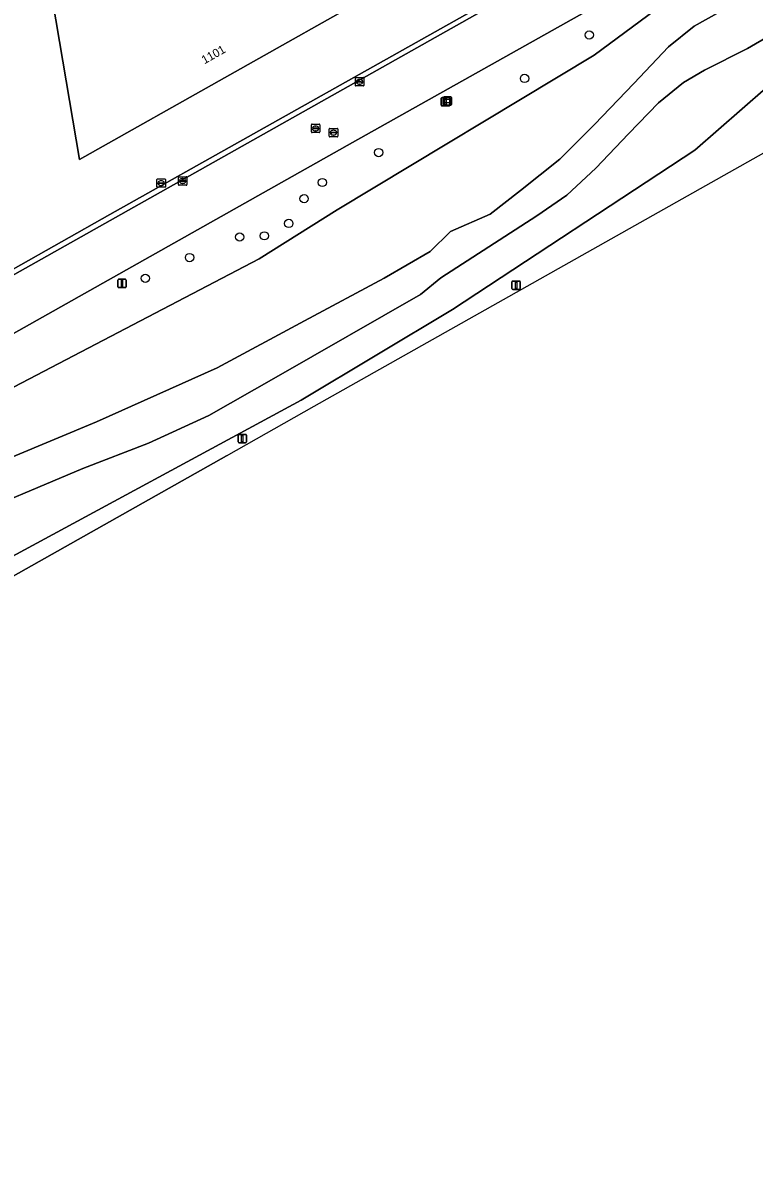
# Model space of a CAD drawing. Extents: x 154324 to 155744, y 382937 to 384188.
# Drawn here: x 154883.8 to 154970, y 383044.6 to 383179.9 of the extents above; entities that cross this region are included whole.
import ezdxf

# ---------------------------------------------------------------- set-up
doc = ezdxf.new("R2010")
doc.units = 0
for name, color, linetype in [('IMGEO_Berm_groen', 7, 'Continuous'), ('IMGEO_Boom', 7, 'Continuous'), ('IMGEO_Brandkraan', 7, 'Continuous'), ('IMGEO_Erf', 7, 'Continuous'), ('IMGEO_Fietspad_gesloten', 7, 'Continuous'), ('IMGEO_Greppel_droge_sloot', 7, 'Continuous'), ('IMGEO_Kolk', 7, 'Continuous'), ('IMGEO_Lichtmast', 7, 'Continuous'), ('IMGEO_Oever', 7, 'Continuous'), ('IMGEO_Pand', 7, 'Continuous'), ('IMGEO_Pand_nummerreeks', 7, 'Continuous'), ('IMGEO_Rijbaan_lokaal_gesloten', 7, 'Continuous'), ('IMGEO_Rijbaan_lokaal_open', 7, 'Continuous'), ('IMGEO_Rioolput', 7, 'Continuous'), ('IMGEO_Verklikker', 7, 'Continuous')]:
    doc.layers.add(name, color=color, linetype=linetype)

msp = doc.modelspace()

# ---------------------------------------------------------------- linework, layer by layer
at = {"layer": 'IMGEO_Berm_groen'}
for points in [[(154991.53, 383204.59), (154991.29, 383204.47), (154988.64, 383202.93), (154972.99, 383194.07), (154922.65, 383165.82), (154870.56, 383136.48), (154807.99, 383101.45), (154807.41, 383100.98), (154799.35, 383096.59), (154796.65, 383095.02), (154788.62, 383090.34), (154781.16, 383085.99), (154710.18, 383044.63)], [(154808.49, 383100.65), (154810.32, 383101.66), (154812.35, 383102.26), (154814.01, 383102.45), (154825.93, 383109.31), (154838.85, 383113.67), (154847.48, 383118.93), (154880.08, 383135.61), (154911.65, 383152.09), (154920.84, 383157.86), (154951.17, 383176.1), (154968.51, 383188.95), (154984.99, 383198.51)], [(154997.79, 383187.52), (154995.02, 383185.46), (154993.14, 383185.64), (154991.72, 383185.98), (154990.93, 383185.04), (154990.62, 383183.53), (154987.22, 383179.75), (154971.41, 383172.23), (154963.03, 383164.91), (154934.46, 383146.12), (154916.59, 383135.42), (154881.58, 383116.49), (154841.44, 383095.73), (154819.25, 383088.82), (154813.1, 383089.87), (154809.33, 383090.4), (154807.25, 383092.6)], [(154806.83, 383071.94), (154907.79, 383128.86), (154918.15, 383134.7), (155000, 383180.84), (155003.66, 383182.91), (155010.14, 383186.73)]]:
    msp.add_lwpolyline(points, dxfattribs=at)
at = {"layer": 'IMGEO_Boom'}
for centre in [(154950.59, 383178.49), (154942.96, 383173.36), (154925.75, 383164.62), (154919.11, 383161.09), (154916.95, 383159.18), (154915.15, 383156.26), (154909.36, 383154.66), (154912.27, 383154.8), (154903.44, 383152.24), (154898.23, 383149.79)]:
    msp.add_circle(centre, 0.489, dxfattribs=at)
at = {"layer": 'IMGEO_Brandkraan'}
for p, q in [((154899.67, 383161.52), (154900.52, 383161.52)), ((154899.59, 383160.59), (154899.59, 383161.44)), ((154900.52, 383160.52), (154899.67, 383160.52)), ((154899.85, 383161.01), (154899.85, 383161.02)), ((154900.29, 383160.97), (154899.89, 383160.97)), ((154899.9, 383161.06), (154900.29, 383161.06)), ((154900.08, 383161.3), (154900.11, 383161.3)), ((154900.1, 383160.74), (154900.08, 383160.74)), ((154900.34, 383161.02), (154900.34, 383161.01)), ((154900.6, 383161.44), (154900.6, 383160.59))]:
    msp.add_line(p, q, dxfattribs=at)
for points in [[(154899.67, 383161.52), (154900.52, 383161.52)], [(154899.59, 383160.59), (154899.59, 383161.44)], [(154900.52, 383160.52), (154899.67, 383160.52)], [(154900.6, 383161.44), (154900.6, 383160.59)]]:
    msp.add_lwpolyline(points, dxfattribs=at)
for centre, radius, start, end in [((154899.67, 383161.44), 0.0765, 91.552, 178.448), ((154899.67, 383161.44), 0.0765, 91.552, 178.448), ((154900.52, 383161.44), 0.0765, 1.552, 88.448), ((154900.52, 383161.44), 0.0765, 1.552, 88.448), ((154899.67, 383160.59), 0.0765, 181.552, 268.448), ((154899.67, 383160.59), 0.0765, 181.552, 268.448), ((154899.89, 383161.02), 0.0403, 85.8775, 175.7526), ((154899.89, 383161.01), 0.0366, 178.938, 274.7102), ((154900.3, 383161.02), 0.0386, 1.7309, 96.639), ((154900.29, 383161.02), 0.043, 264.8664, 352.4533), ((154900.52, 383160.59), 0.0765, 271.552, 358.448), ((154900.52, 383160.59), 0.0765, 271.552, 358.448)]:
    msp.add_arc(centre, radius, start, end, dxfattribs=at)
for centre, major_axis, ratio, start_param, end_param in [((154900.08, 383161.02), (-0.387, 0.002), 0.722429, 4.712389, 7.853982), ((154900.11, 383161.02), (-0.39, 0.002), 0.717154, 1.570796, 4.712389)]:
    msp.add_ellipse(centre, major_axis=major_axis, ratio=ratio, start_param=start_param, end_param=end_param, dxfattribs=at)
at = {"layer": 'IMGEO_Erf'}
for points in [[(154925.91, 383183.81), (154890.47, 383163.81), (154885.3, 383194.22)], [(154813.97, 383112.22), (154836.96, 383125.07), (154866.96, 383142.01), (154876.91, 383147.63), (154894.04, 383157.31), (154944.86, 383185.9), (154948.91, 383188.11)]]:
    msp.add_lwpolyline(points, dxfattribs=at)
at = {"layer": 'IMGEO_Fietspad_gesloten'}
msp.add_lwpolyline([(154806.83, 383071.94), (154907.79, 383128.86), (154806.83, 383071.94), (154806.83, 383071.94)], dxfattribs=at)
at = {"layer": 'IMGEO_Greppel_droge_sloot'}
for points in [[(154967.67, 383182.15), (154962.95, 383179.53), (154959.93, 383177.1), (154955.85, 383172.76), (154951.2, 383167.94), (154947.13, 383163.84), (154942.48, 383160.15), (154938.92, 383157.34), (154934.23, 383155.33), (154931.84, 383152.94), (154926.39, 383149.8), (154917.01, 383144.77), (154906.7, 383139.24), (154892.46, 383132.87), (154882.48, 383128.68), (154872.51, 383124.16), (154861.95, 383119.21), (154853.15, 383115.28), (154841, 383110.46), (154834.68, 383107.78), (154825.71, 383103.59), (154818, 383100.36)], [(154819.59, 383098.03), (154824.7, 383100.04), (154831.91, 383102.98), (154835.98, 383104.78), (154843.85, 383108.3), (154854.83, 383112.7), (154859.94, 383114.75), (154866.14, 383116.8), (154875.9, 383121.08), (154890.86, 383127.36), (154898.61, 383130.34), (154905.7, 383133.61), (154913.66, 383138.13), (154930.67, 383147.9), (154933.1, 383149.86), (154944.41, 383157.15), (154947.93, 383159.59), (154951.37, 383162.77), (154955.22, 383166.83), (154958.74, 383170.48), (154961.71, 383172.87), (154964.19, 383174.33), (154969.26, 383176.89), (154971.9, 383178.44)]]:
    msp.add_lwpolyline(points, dxfattribs=at)
at = {"layer": 'IMGEO_Kolk'}
for p, q in [((154923, 383172.54), (154923, 383173.4)), ((154923.07, 383173.47), (154923.92, 383173.47)), ((154923.92, 383172.47), (154923.07, 383172.47)), ((154923.25, 383172.96), (154923.25, 383172.98)), ((154923.69, 383172.93), (154923.29, 383172.93)), ((154923.3, 383173.01), (154923.69, 383173.01)), ((154923.48, 383173.25), (154923.51, 383173.25)), ((154923.51, 383172.69), (154923.48, 383172.69)), ((154923.74, 383172.98), (154923.74, 383172.96)), ((154924, 383173.4), (154924, 383172.54)), ((154902.13, 383160.84), (154902.13, 383161.69)), ((154902.21, 383161.77), (154903.06, 383161.77)), ((154902.62, 383161.55), (154902.64, 383161.55)), ((154903.13, 383161.69), (154903.13, 383160.84)), ((154903.06, 383160.77), (154902.21, 383160.77)), ((154902.39, 383161.26), (154902.39, 383161.27)), ((154902.43, 383161.31), (154902.83, 383161.31)), ((154902.83, 383161.22), (154902.43, 383161.22)), ((154902.64, 383160.99), (154902.62, 383160.99)), ((154902.87, 383161.27), (154902.87, 383161.26))]:
    msp.add_line(p, q, dxfattribs=at)
for points in [[(154923, 383172.54), (154923, 383173.4)], [(154923.07, 383173.47), (154923.92, 383173.47)], [(154923.92, 383172.47), (154923.07, 383172.47)], [(154924, 383173.4), (154924, 383172.54)], [(154902.13, 383160.84), (154902.13, 383161.69)], [(154902.21, 383161.77), (154903.06, 383161.77)], [(154903.13, 383161.69), (154903.13, 383160.84)], [(154903.06, 383160.77), (154902.21, 383160.77)]]:
    msp.add_lwpolyline(points, dxfattribs=at)
for centre, radius, start, end in [((154923.07, 383173.4), 0.0765, 91.552, 178.448), ((154923.07, 383173.4), 0.0765, 91.552, 178.448), ((154923.07, 383172.55), 0.0765, 181.552, 268.448), ((154923.07, 383172.55), 0.0765, 181.552, 268.448), ((154923.29, 383172.97), 0.0403, 85.8775, 175.7526), ((154923.29, 383172.96), 0.0366, 178.938, 274.7102), ((154923.7, 383172.98), 0.0386, 1.7309, 96.639), ((154923.7, 383172.97), 0.043, 264.8664, 352.4533), ((154923.92, 383173.4), 0.0765, 1.552, 88.448), ((154923.92, 383173.4), 0.0765, 1.552, 88.448), ((154923.92, 383172.55), 0.0765, 271.552, 358.448), ((154923.92, 383172.55), 0.0765, 271.552, 358.448), ((154902.21, 383161.69), 0.0765, 91.552, 178.448), ((154902.21, 383161.69), 0.0765, 91.552, 178.448), ((154903.06, 383161.69), 0.0765, 1.552, 88.448), ((154903.06, 383161.69), 0.0765, 1.552, 88.448), ((154902.21, 383160.84), 0.0765, 181.552, 268.448), ((154902.21, 383160.84), 0.0765, 181.552, 268.448), ((154902.43, 383161.27), 0.0403, 85.8775, 175.7526), ((154902.43, 383161.26), 0.0366, 178.938, 274.7102), ((154902.84, 383161.27), 0.0386, 1.7309, 96.639), ((154902.83, 383161.27), 0.043, 264.8664, 352.4533), ((154903.06, 383160.84), 0.0765, 271.552, 358.448), ((154903.06, 383160.84), 0.0765, 271.552, 358.448)]:
    msp.add_arc(centre, radius, start, end, dxfattribs=at)
for centre, major_axis, ratio, start_param, end_param in [((154923.48, 383172.97), (-0.387, 0.002), 0.722429, 4.712389, 7.853982), ((154923.51, 383172.97), (-0.39, 0.002), 0.717154, 1.570796, 4.712389), ((154902.62, 383161.27), (-0.387, 0.002), 0.722429, 4.712389, 7.853982), ((154902.64, 383161.27), (-0.39, 0.002), 0.717154, 1.570796, 4.712389)]:
    msp.add_ellipse(centre, major_axis=major_axis, ratio=ratio, start_param=start_param, end_param=end_param, dxfattribs=at)
at = {"layer": 'IMGEO_Lichtmast'}
for p, q in [((154933.14, 383170.22), (154933.14, 383171.02)), ((154933.14, 383171.02), (154933.14, 383170.22)), ((154933.24, 383171.12), (154934.03, 383171.12)), ((154934.03, 383171.12), (154933.24, 383171.12)), ((154934.13, 383171.02), (154934.13, 383170.22)), ((154934.13, 383170.22), (154934.13, 383171.02)), ((154934.03, 383170.12), (154933.24, 383170.12)), ((154933.24, 383170.12), (154934.03, 383170.12)), ((154894.98, 383148.79), (154894.98, 383149.59)), ((154894.98, 383149.59), (154894.98, 383148.79)), ((154895.08, 383149.69), (154895.87, 383149.69)), ((154895.87, 383149.69), (154895.08, 383149.69)), ((154895.97, 383149.59), (154895.97, 383148.79)), ((154895.97, 383148.79), (154895.97, 383149.59)), ((154941.46, 383148.57), (154941.46, 383149.37)), ((154941.46, 383149.37), (154941.46, 383148.57)), ((154941.56, 383149.47), (154942.35, 383149.47)), ((154942.35, 383149.47), (154941.56, 383149.47)), ((154942.45, 383149.37), (154942.45, 383148.57)), ((154942.45, 383148.57), (154942.45, 383149.37)), ((154895.87, 383148.69), (154895.08, 383148.69)), ((154895.08, 383148.69), (154895.87, 383148.69)), ((154942.35, 383148.47), (154941.56, 383148.47)), ((154941.56, 383148.47), (154942.35, 383148.47)), ((154909.17, 383130.49), (154909.17, 383131.29)), ((154909.17, 383131.29), (154909.17, 383130.49)), ((154909.27, 383131.39), (154910.06, 383131.39)), ((154910.06, 383131.39), (154909.27, 383131.39)), ((154910.06, 383130.39), (154909.27, 383130.39)), ((154909.27, 383130.39), (154910.06, 383130.39)), ((154910.16, 383131.29), (154910.16, 383130.49)), ((154910.16, 383130.49), (154910.16, 383131.29))]:
    msp.add_line(p, q, dxfattribs=at)
for points in [[(154933.56, 383171), (154933.71, 383171), (154933.71, 383170.25), (154933.56, 383170.25), (154933.56, 383171)], [(154895.4, 383149.57), (154895.55, 383149.57), (154895.55, 383148.82), (154895.4, 383148.82), (154895.4, 383149.57)], [(154941.88, 383149.35), (154942.03, 383149.35), (154942.03, 383148.6), (154941.88, 383148.6), (154941.88, 383149.35)], [(154909.59, 383131.27), (154909.74, 383131.27), (154909.74, 383130.52), (154909.59, 383130.52), (154909.59, 383131.27)]]:
    msp.add_lwpolyline(points, dxfattribs=at)
for centre, start, end in [((154933.24, 383171.02), 90, 180), ((154933.24, 383171.02), 90, 180), ((154934.03, 383171.02), 0, 90), ((154934.03, 383171.02), 360, 90), ((154933.24, 383170.22), 180, 270), ((154933.24, 383170.22), 180, 270), ((154934.03, 383170.22), 270, 0), ((154934.03, 383170.22), 270, 0), ((154895.08, 383149.59), 90, 180), ((154895.08, 383149.59), 90, 180), ((154895.87, 383149.59), 0, 90), ((154895.87, 383149.59), 360, 90), ((154941.56, 383149.37), 90, 180), ((154941.56, 383149.37), 90, 180), ((154942.35, 383149.37), 0, 90), ((154942.35, 383149.37), 360, 90), ((154895.08, 383148.79), 180, 270), ((154895.08, 383148.79), 180, 270), ((154895.87, 383148.79), 270, 0), ((154895.87, 383148.79), 270, 0), ((154941.56, 383148.57), 180, 270), ((154941.56, 383148.57), 180, 270), ((154942.35, 383148.57), 270, 0), ((154942.35, 383148.57), 270, 0), ((154909.27, 383131.29), 90, 180), ((154909.27, 383131.29), 90, 180), ((154909.27, 383130.49), 180, 270), ((154909.27, 383130.49), 180, 270), ((154910.06, 383131.29), 0, 90), ((154910.06, 383131.29), 360, 90), ((154910.06, 383130.49), 270, 0), ((154910.06, 383130.49), 270, 0)]:
    msp.add_arc(centre, 0.1, start, end, dxfattribs=at)
at = {"layer": 'IMGEO_Oever'}
for points in [[(154984.99, 383198.51), (154968.51, 383188.95), (154951.17, 383176.1), (154920.84, 383157.86), (154911.65, 383152.09), (154880.08, 383135.61), (154847.48, 383118.93), (154838.85, 383113.67), (154825.93, 383109.31), (154814.01, 383102.45), (154814.3, 383101.66), (154811.41, 383101.47), (154810.32, 383101.17), (154808.07, 383099.87)], [(154934.46, 383146.12), (154963.03, 383164.91), (154971.41, 383172.23), (154987.22, 383179.75), (154990.62, 383183.53), (154990.93, 383185.04), (154991.72, 383185.98), (154993.14, 383185.64), (154995.02, 383185.46), (154997.79, 383187.52)], [(154818, 383100.36), (154825.71, 383103.59), (154834.68, 383107.78), (154841, 383110.46), (154853.15, 383115.28), (154861.95, 383119.21), (154872.51, 383124.16), (154882.48, 383128.68), (154892.46, 383132.87), (154906.7, 383139.24), (154917.01, 383144.77), (154926.39, 383149.8), (154931.84, 383152.94), (154934.23, 383155.33), (154938.92, 383157.34), (154942.48, 383160.15), (154947.13, 383163.84), (154951.2, 383167.94), (154955.85, 383172.76), (154959.93, 383177.1), (154962.95, 383179.53), (154967.67, 383182.15)], [(154971.9, 383178.44), (154969.26, 383176.89), (154964.19, 383174.33), (154961.71, 383172.87), (154958.74, 383170.48), (154955.22, 383166.83), (154951.37, 383162.77), (154947.93, 383159.59), (154944.41, 383157.15), (154933.1, 383149.86), (154930.67, 383147.9), (154913.66, 383138.13), (154905.7, 383133.61), (154898.61, 383130.34), (154890.86, 383127.36), (154875.9, 383121.08), (154866.14, 383116.8), (154859.94, 383114.75), (154854.83, 383112.7), (154843.85, 383108.3), (154835.98, 383104.78), (154831.91, 383102.98), (154824.7, 383100.04), (154819.59, 383098.03)], [(154806.33, 383094.16), (154807.25, 383092.6), (154809.33, 383090.4), (154813.1, 383089.87), (154819.25, 383088.82), (154841.44, 383095.73), (154881.58, 383116.49), (154916.59, 383135.42), (154934.46, 383146.12)]]:
    msp.add_lwpolyline(points, dxfattribs=at)
at = {"layer": 'IMGEO_Pand'}
msp.add_lwpolyline([(154885.3, 383194.22), (154890.47, 383163.81), (154925.91, 383183.81)], dxfattribs=at)
at = {"layer": 'IMGEO_Rijbaan_lokaal_gesloten'}
for points in [[(154710.18, 383044.63), (154781.16, 383085.99), (154788.62, 383090.34), (154796.65, 383095.02), (154799.35, 383096.59), (154807.41, 383100.98), (154807.99, 383101.45), (154870.56, 383136.48), (154922.65, 383165.82), (154972.99, 383194.07), (154988.64, 383202.93), (154991.29, 383204.47), (154991.53, 383204.59), (154994.57, 383206.14), (154995.34, 383206.58), (155027.96, 383225.07), (155055.76, 383240.82)], [(154985.26, 383208.05), (154967.73, 383198.1), (154950.17, 383188.22), (154949.49, 383187.84), (154947.08, 383186.48), (154867.23, 383141.52), (154850.15, 383131.9), (154814.79, 383112.01)]]:
    msp.add_lwpolyline(points, dxfattribs=at)
at = {"layer": 'IMGEO_Rijbaan_lokaal_open'}
for points in [[(154948.91, 383188.11), (154944.86, 383185.9), (154894.04, 383157.31), (154876.91, 383147.63), (154866.96, 383142.01), (154836.96, 383125.07), (154813.97, 383112.22)], [(154814.79, 383112.01), (154850.15, 383131.9), (154867.23, 383141.52), (154947.08, 383186.48)]]:
    msp.add_lwpolyline(points, dxfattribs=at)
at = {"layer": 'IMGEO_Rioolput'}
for p, q in [((154917.81, 383167.05), (154917.81, 383167.9)), ((154917.88, 383167.97), (154918.74, 383167.97)), ((154918.74, 383166.97), (154917.88, 383166.97)), ((154918.07, 383167.47), (154918.07, 383167.48)), ((154918.11, 383167.52), (154918.51, 383167.52)), ((154918.51, 383167.43), (154918.11, 383167.43)), ((154918.32, 383167.19), (154918.29, 383167.19)), ((154918.3, 383167.75), (154918.32, 383167.75)), ((154918.55, 383167.48), (154918.55, 383167.47)), ((154918.81, 383167.9), (154918.81, 383167.05)), ((154919.92, 383166.54), (154919.92, 383167.4)), ((154919.99, 383167.47), (154920.84, 383167.47)), ((154920.18, 383166.96), (154920.18, 383166.98)), ((154920.22, 383167.01), (154920.62, 383167.01)), ((154920.61, 383166.93), (154920.22, 383166.93)), ((154920.41, 383167.25), (154920.43, 383167.25)), ((154920.66, 383166.98), (154920.66, 383166.96)), ((154920.92, 383167.4), (154920.92, 383166.54)), ((154920.84, 383166.47), (154919.99, 383166.47)), ((154920.43, 383166.69), (154920.4, 383166.69))]:
    msp.add_line(p, q, dxfattribs=at)
for points in [[(154917.81, 383167.05), (154917.81, 383167.9)], [(154917.88, 383167.97), (154918.74, 383167.97)], [(154918.74, 383166.97), (154917.88, 383166.97)], [(154918.81, 383167.9), (154918.81, 383167.05)], [(154919.92, 383166.54), (154919.92, 383167.4)], [(154919.99, 383167.47), (154920.84, 383167.47)], [(154920.92, 383167.4), (154920.92, 383166.54)], [(154920.84, 383166.47), (154919.99, 383166.47)]]:
    msp.add_lwpolyline(points, dxfattribs=at)
for centre, radius, start, end in [((154917.89, 383167.9), 0.0765, 91.552, 178.448), ((154917.89, 383167.9), 0.0765, 91.552, 178.448), ((154917.89, 383167.05), 0.0765, 181.552, 268.448), ((154917.89, 383167.05), 0.0765, 181.552, 268.448), ((154918.11, 383167.48), 0.0403, 85.8775, 175.7526), ((154918.1, 383167.47), 0.0366, 178.938, 274.7102), ((154918.51, 383167.48), 0.0386, 1.7309, 96.639), ((154918.51, 383167.47), 0.043, 264.8664, 352.4533), ((154918.73, 383167.9), 0.0765, 1.552, 88.448), ((154918.73, 383167.9), 0.0765, 1.552, 88.448), ((154918.73, 383167.05), 0.0765, 271.552, 358.448), ((154918.73, 383167.05), 0.0765, 271.552, 358.448), ((154919.99, 383167.39), 0.0765, 91.552, 178.448), ((154919.99, 383167.39), 0.0765, 91.552, 178.448), ((154920.22, 383166.97), 0.0403, 85.8775, 175.7526), ((154920.21, 383166.96), 0.0366, 178.938, 274.7102), ((154920.62, 383166.97), 0.043, 264.8664, 352.4533), ((154920.62, 383166.97), 0.0386, 1.7309, 96.639), ((154920.84, 383167.39), 0.0765, 1.552, 88.448), ((154920.84, 383167.39), 0.0765, 1.552, 88.448), ((154919.99, 383166.54), 0.0765, 181.552, 268.448), ((154919.99, 383166.54), 0.0765, 181.552, 268.448), ((154920.84, 383166.54), 0.0765, 271.552, 358.448), ((154920.84, 383166.54), 0.0765, 271.552, 358.448)]:
    msp.add_arc(centre, radius, start, end, dxfattribs=at)
for centre, major_axis, ratio, start_param, end_param in [((154918.3, 383167.47), (-0.387, 0.002), 0.722429, 4.712389, 7.853982), ((154918.32, 383167.47), (-0.39, 0.002), 0.717154, 1.570796, 4.712389), ((154920.4, 383166.97), (-0.387, 0.002), 0.722429, 4.712389, 7.853982), ((154920.43, 383166.97), (-0.39, 0.002), 0.717154, 1.570796, 4.712389)]:
    msp.add_ellipse(centre, major_axis=major_axis, ratio=ratio, start_param=start_param, end_param=end_param, dxfattribs=at)
at = {"layer": 'IMGEO_Verklikker'}
for p, q in [((154933.36, 383170.3), (154933.36, 383171.1)), ((154933.36, 383171.1), (154933.36, 383170.3)), ((154933.46, 383171.2), (154934.25, 383171.2)), ((154934.25, 383171.2), (154933.46, 383171.2)), ((154934.35, 383171.1), (154934.35, 383170.3)), ((154934.35, 383170.3), (154934.35, 383171.1)), ((154934.25, 383170.2), (154933.46, 383170.2)), ((154933.46, 383170.2), (154934.25, 383170.2))]:
    msp.add_line(p, q, dxfattribs=at)
for points in [[(154933.46, 383170.93), (154934.25, 383170.93), (154934.25, 383170.47), (154933.46, 383170.47), (154933.46, 383170.93)], [(154933.53, 383170.87), (154933.53, 383170.53), (154934.19, 383170.53), (154934.19, 383170.87), (154933.53, 383170.87)]]:
    msp.add_lwpolyline(points, dxfattribs=at)
for centre, start, end in [((154933.46, 383171.1), 90, 180), ((154933.46, 383171.1), 90, 180), ((154934.25, 383171.1), 0, 90), ((154934.25, 383171.1), 360, 90), ((154933.46, 383170.3), 180, 270), ((154933.46, 383170.3), 180, 270), ((154934.25, 383170.3), 270, 0), ((154934.25, 383170.3), 270, 0)]:
    msp.add_arc(centre, 0.1, start, end, dxfattribs=at)

# ---------------------------------------------------------------- texts
at = {"layer": 'IMGEO_Pand_nummerreeks'}
msp.add_text('1101', height=1, rotation=29.4386, dxfattribs=at).set_placement((154905.2, 383175.02))

doc.saveas('drawing.dxf')
